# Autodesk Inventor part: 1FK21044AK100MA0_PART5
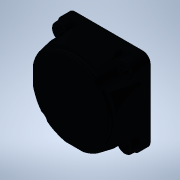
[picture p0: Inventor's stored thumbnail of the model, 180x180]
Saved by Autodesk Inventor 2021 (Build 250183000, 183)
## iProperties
Created: 2025-04
Part Number: 1FK21044AK100MA0_PART5
Material: Generic
Catalog Web Link: www.3dfindit.com
Description: -Servo synchronous motor
Document SubType Name: Modeling
Designer: psAdmin
Mass: 3.92604 g
Surface Area: 17.9521 cm^2
Volume: 3.92604 cm^3
Density: 1 g/cm^3
Appearance: PSOLRGB-48-56-69
Category: PARTsolutions
Title: 1FK21044AK100MA0_PART5
Author: Cadenas PARTsolutions
Comments: Servo synchronous motor
Sending System: PARTsolutions
Preprocessor: ST-DEVELOPER v19.3
PSOL_IDENT_0: {$CADENAS_DATA/23d-libs/siemens_ag/_cat_/5e/d8/1fk21044ak100ma0.prj},213 {VTYP=3D},{NB=1FK21044AK100
PSOL_IDENT_1: MA0_PART5},{LINA=1FK21044AK100MA0_PART5},{NN=1FK21044AK100MA0_PART5},{NOPRJ=TRUE},{DATE=19.08.2025 1
PSOL_IDENT_2: 4:00:41},{GEOMDATE=30.07.2025 02:00:53},{VERSION=},{LINEID=10},{WBVAR=},{WBNUMERIC=}  {NB=1FK21044AK
PSOL_IDENT_3: 100MA0_PART5},{LINA=1FK21044AK100MA0_PART5},{KT=DUMMY},{PREVIEW=../../../_pool_/cb/72/p_d211_xx_0043
PSOL_IDENT_4: 4j.png},{DESCSHORT=SIMOTICS S-1FK2 HD, SINAMICS S210 3AC 400V-480V, 0.95 Nm, 6000 rpm},{DESCLONG=SIM
PSOL_IDENT_5: OTICS S-1FK2 HD servo motor M0=1.27 Nm; PN = 0.6 kW at nN=6000 rpm (380-480 V); PN = 0.4 kW at nN=30
PSOL_IDENT_6: 00 rpm (200-240 V); with holding brake; degree of protection IP64; cylindrical shaft D19x40mm; absol
PSOL_IDENT_7: ute encoder 22-bit + 12-bit multiturn (encoder AM22DQC); with OCC interface; plug size M17, rotatabl
PSOL_IDENT_8: e; SIMOTICS S-1FK2 servomotorfor a wide range of uses in industrial environments. SIMOTICS S‑1FK2 se
PSOL_IDENT_9: rvomotors are compact synchronous motors with a high dynamic performance that set themselves apart a
PSOL_IDENT_10: s a result of their high power density, degree of protection and overload capability. The motors are
PSOL_IDENT_11: available in two variants: as High Dynamic variant (highest dynamic performance as a result of the
PSOL_IDENT_12: low intrinsic moment of inertia for applications demanding a high dynamic performance with low moved
PSOL_IDENT_13: masses) - and as Compact variant (precise and stable closed-loop control for medium up to large mov
PSOL_IDENT_14: ed masses as a result of a medium intrinsic moment of inertia). SIMOTICSS‑1FK2 servomotors fully exp
PSOL_IDENT_15: loit their strengths in a system with the SINAMICSS210 frequency converter and simple connection usi
PSOL_IDENT_16: ng the one cable connection (OCC). Advantages include the short control and positioning times, fast
PSOL_IDENT_17: and precise correction of disturbing quantities as well as stable control with a high dynamic perfor
PSOL_IDENT_18: mance. The servo motors can be configured to address a wide range of requirements. For example with
PSOL_IDENT_19: and without holding brake, IP64 or IP65 degree of protection, singleturn or multiturn absolute encod
PSOL_IDENT_20: ers - to name just a few. Further, the servomotors are available in different shaft heights extendin
PSOL_IDENT_21: g from 20 to 100. A shaft sealing ring is available to achieve an IP65 degree of protection and for
PSOL_IDENT_22: subsequent mounting at the motor or as spare part. SIMOTICS - the optimum motor for each and every m
PSOL_IDENT_23: otion control application.},{INTNO=804766910005},{SUPPLIERALTNO=1FK2104-4AK10-0MA0},{MANUID=1FK21044
PSOL_IDENT_24: AK100MA0},{MANUNAME=Siemens},{MANUTYPEDESC=Synchronous motor 1FK2-HD 1,27 Nm},{AAU732=SIMOTICS},{AAO
PSOL_IDENT_25: 057=S-1FK2},{AAU734=SIMOTICS S-1FK2 HD servo motor M0=1.27 Nm; PN = 0.6 kW at nN=6000 rpm (380-480 V
PSOL_IDENT_26: ); PN = 0.4 kW at nN=3000 rpm (200-240 V); with holding brake; degree of protection IP64; cylindrica
PSOL_IDENT_27: l shaft D19x40mm; absolute encoder 22-bit + 12-bit multiturn (encoder AM22DQC); with OCC interface;
PSOL_IDENT_28: plug size M17, rotatable;},{AAW338=Synchronous motor 1FK2-HD 1,27 Nm},{AAO742=SIMOTICS},{AAO663=4042
PSOL_IDENT_29: 948691076},{NOCUPEROU=1},{PRICEQUANTITY=1},{QUANTITYMIN=1},{QUANTITYINT=1},{CTN=85015100},{COO=DE},{
PSOL_IDENT_30: AAO676=1FK2104-4AK10-0MA0},{AAO677=Siemens AG},{ORDERUNIT=C62},{CONTENTUNIT=C62}
NB: 1FK21044AK100MA0_PART5
NT: Servo synchronous motor
NBSYN: $MANUID._PART5
LINA: 1FK21044AK100MA0_PART5
CATALOG: SIEMENS
PREVIEW: ../../../_pool_/cb/72/p_d211_xx_00434j.png
DESCSHORT: SIMOTICS S-1FK2 HD, SINAMICS S210 3AC 400V-480V, 0.95 Nm, 6000 rpm
DESCLONG: SIMOTICS S-1FK2 HD servo motor M0=1.27 Nm; PN = 0.6 kW at nN=6000 rpm (380-480 V); PN = 0.4 kW at nN=3000 rpm (200-240 V); with holding brake; degree of protect
INTNO: 804766910005
SUPPLIERALTNO: 1FK2104-4AK10-0MA0
MANUID: 1FK21044AK100MA0
MANUNAME: Siemens
MANUTYPEDESC: Synchronous motor 1FK2-HD 1,27 Nm
AAU732: SIMOTICS
AAO057: S-1FK2
AAU734: SIMOTICS S-1FK2 HD servo motor M0=1.27 Nm; PN = 0.6 kW at nN=6000 rpm (380-480 V); PN = 0.4 kW at nN=3000 rpm (200-240 V); with holding brake; degree of protect
AAW338: Synchronous motor 1FK2-HD 1,27 Nm
AAO742: SIMOTICS
AAO663: 4042948691076.0
NOCUPEROU: 1
PRICEQUANTITY: 1
QUANTITYMIN: 1
QUANTITYINT: 1
CTN: 85015100
COO: DE
ARTICLENO: 1FK21044AK100MA0_PART5
BOMINFO: 1FK21044AK100MA0_PART5
CREATOR: CADENAS GmbH
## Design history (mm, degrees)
feature "2025_04_17_15_35_41_0905"
body "Solid1"
